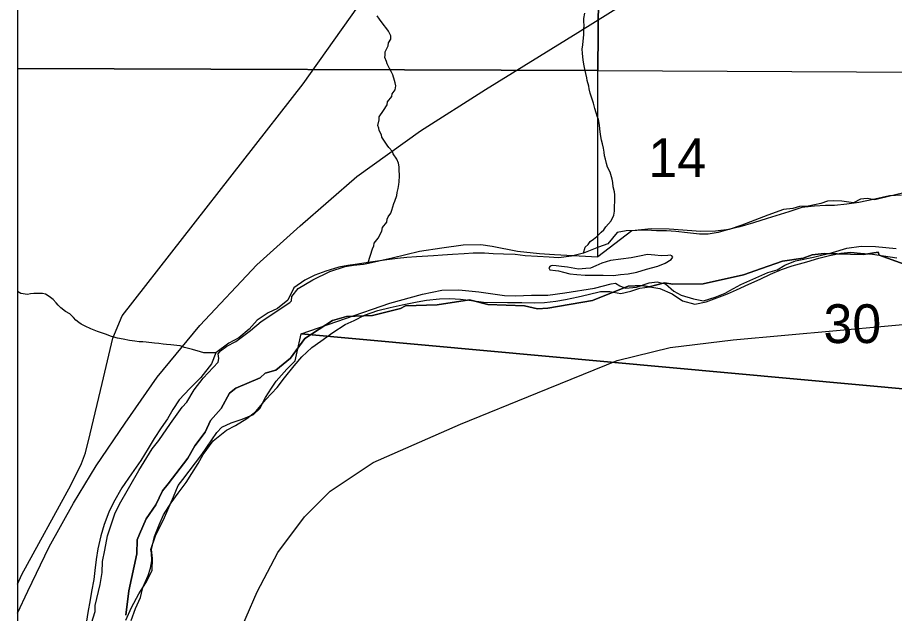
# Model space of a CAD drawing. Extents: x 0 to 34, y 0 to 22.
# Drawn here: x 16.6 to 17.545, y 18.951 to 19.593 of the extents above; entities that cross this region are included whole.
import ezdxf

# ---------------------------------------------------------------- set-up
doc = ezdxf.new("R2010")
doc.units = 0
for name, color, linetype in [('GM_X_County_Road', 7, 'Continuous'), ('GM_X_Major_River', 7, 'Continuous'), ('GM_X_Minor_River', 7, 'Continuous'), ('GM_X_Rail_Line', 7, 'Continuous'), ('GM_X_Section', 7, 'Continuous'), ('GM_X_Section_Text', 7, 'Continuous'), ('GM_X_Unincorporated', 7, 'Continuous'), ('SC_Scratch1', 7, 'Continuous'), ('SH_Border', 7, 'Continuous'), ('SH_Cut_Line', 7, 'Continuous')]:
    doc.layers.add(name, color=color, linetype=linetype)

msp = doc.modelspace()

# ---------------------------------------------------------------- linework, layer by layer
at = {"layer": 'GM_X_County_Road'}
for points in [[(16.59999, 18.98204), (16.60479, 18.99269), (16.65763, 19.08895), (16.66897, 19.11241), (16.67314, 19.12394), (16.67838, 19.14444), (16.69117, 19.19857), (16.70268, 19.24752), (16.71279, 19.27147), (16.90778, 19.52198), (16.96699, 19.60505), (16.99179, 19.63189), (17.03917, 19.66999), (17.08216, 19.70081), (17.10542, 19.71065), (17.1286, 19.71373), (17.2334, 19.71372), (17.27092, 19.71252), (17.32928, 19.71064), (17.33924, 19.71033), (17.44315, 19.70692), (17.53189, 19.70575), (17.64432, 19.69971)], [(16.83476, 18.91919), (16.85845, 18.97378), (16.88052, 19.01652), (16.90932, 19.05485), (16.9372, 19.0825), (16.98343, 19.11339), (17.07751, 19.15474), (17.16067, 19.18866), (17.24639, 19.2235), (17.30381, 19.23758), (17.3716, 19.24557), (17.59438, 19.26601)]]:
    msp.add_lwpolyline(points, dxfattribs=at)
at = {"layer": 'GM_X_Major_River'}
for points in [[(17.55306, 19.40187), (17.54015, 19.40098), (17.52415, 19.39749), (17.50701, 19.39402), (17.49407, 19.392), (17.48077, 19.39074), (17.47129, 19.39055), (17.45914, 19.39002), (17.44545, 19.38839), (17.4317, 19.38372), (17.40804, 19.37658), (17.39354, 19.37192), (17.37866, 19.36765), (17.36646, 19.36485), (17.3554, 19.36165), (17.34474, 19.35958), (17.33526, 19.35976), (17.32239, 19.36115), (17.3099, 19.36254), (17.29968, 19.36312), (17.28906, 19.36333), (17.27807, 19.36393), (17.26783, 19.36375), (17.25606, 19.36322), (17.24654, 19.3615), (17.23643, 19.34916), (17.2265, 19.34555), (17.21006, 19.33903), (17.1971, 19.33586), (17.18341, 19.33423), (17.17318, 19.33481), (17.16068, 19.33544), (17.14742, 19.33646), (17.13645, 19.33782), (17.12394, 19.33806), (17.11295, 19.33866), (17.10348, 19.33923), (17.09134, 19.33908), (17.08147, 19.33852), (17.06893, 19.33762), (17.05831, 19.33707), (17.04843, 19.3365), (17.0302, 19.33534), (17.01956, 19.33441), (17.00968, 19.33347), (16.99828, 19.33217), (16.97812, 19.32914), (16.9667, 19.32747), (16.95605, 19.32577), (16.94653, 19.32406), (16.93241, 19.31978), (16.92056, 19.31545), (16.90983, 19.30995), (16.89791, 19.30183), (16.89157, 19.28865), (16.88039, 19.27936), (16.87006, 19.275), (16.85851, 19.26687), (16.84959, 19.25716), (16.83841, 19.24787), (16.82767, 19.242), (16.8138, 19.23163), (16.80901, 19.21993), (16.79771, 19.20495), (16.78572, 19.1934), (16.77409, 19.18108), (16.76743, 19.17057), (16.76153, 19.16042), (16.75489, 19.15067), (16.74745, 19.13941), (16.74078, 19.12852), (16.73294, 19.11574), (16.72278, 19.10112), (16.71261, 19.08611), (16.70357, 19.07032), (16.69843, 19.05978), (16.69323, 19.04657), (16.68995, 19.03447), (16.68663, 19.02047), (16.68487, 19.00872), (16.6835, 18.99696), (16.68216, 18.98711), (16.67962, 18.97423), (16.67788, 18.96324)], [(16.71693, 18.94347), (16.72289, 18.95703), (16.73077, 18.97171), (16.73822, 18.98372), (16.74532, 18.99689), (16.74558, 19.00981), (16.74427, 19.01972), (16.74758, 19.03372), (16.75277, 19.04617), (16.75754, 19.0571), (16.76576, 19.06986), (16.77318, 19.08036), (16.78176, 19.09197), (16.78803, 19.10174), (16.79469, 19.11225), (16.8002, 19.12202), (16.81074, 19.13664), (16.82538, 19.14814), (16.83497, 19.15327), (16.84726, 19.16102), (16.8569, 19.16843), (16.86778, 19.18152), (16.8798, 19.19421), (16.88797, 19.2047), (16.8981, 19.2178), (16.90664, 19.22752), (16.91747, 19.23757), (16.92708, 19.24423), (16.93979, 19.25348), (16.95324, 19.26234), (16.96281, 19.26672), (16.97392, 19.2722), (16.98844, 19.27724), (17.00178, 19.28077), (17.01474, 19.28356), (17.03073, 19.28667), (17.04101, 19.28837), (17.05507, 19.28999), (17.06608, 19.29016), (17.07744, 19.28955), (17.08955, 19.28817), (17.10241, 19.2864), (17.12819, 19.28589), (17.14374, 19.28597), (17.15739, 19.2857), (17.16802, 19.28587), (17.18019, 19.28753), (17.19084, 19.28923), (17.20455, 19.292), (17.21522, 19.29445), (17.22857, 19.29799), (17.23842, 19.29779), (17.25052, 19.29566), (17.26119, 19.29811), (17.27111, 19.30133), (17.28177, 19.30303), (17.29235, 19.30092), (17.30588, 19.29533), (17.31711, 19.28788), (17.33031, 19.2842), (17.3425, 19.28663), (17.35396, 19.29096), (17.36543, 19.2953), (17.375, 19.29967), (17.3884, 19.30588), (17.40065, 19.31134), (17.41175, 19.31644), (17.42361, 19.32153), (17.43507, 19.32549), (17.45109, 19.32973), (17.46406, 19.33366), (17.47551, 19.33686), (17.48769, 19.33928), (17.49833, 19.34021), (17.50893, 19.33924), (17.52181, 19.33823), (17.53353, 19.33648), (17.5479, 19.3343)], [(17.1801, 19.32061), (17.18312, 19.32017), (17.18878, 19.31854), (17.19557, 19.31688), (17.20315, 19.31636), (17.21185, 19.31542), (17.2202, 19.31564), (17.23157, 19.31542), (17.24257, 19.3152), (17.25017, 19.31619), (17.25853, 19.31679), (17.26768, 19.31889), (17.27798, 19.32211), (17.29018, 19.32529), (17.29821, 19.32856), (17.30474, 19.33223), (17.30669, 19.33485), (17.30558, 19.33639), (17.3037, 19.33719), (17.30104, 19.33686), (17.29382, 19.33624), (17.28701, 19.33714), (17.27906, 19.33767), (17.27068, 19.33594), (17.26154, 19.33422), (17.25051, 19.33291), (17.23948, 19.33123), (17.22994, 19.32838), (17.22344, 19.32546), (17.21769, 19.32291), (17.21276, 19.32263), (17.20478, 19.32203), (17.19306, 19.32416), (17.18663, 19.32467), (17.18058, 19.32554), (17.17641, 19.32601)], [(17.17641, 19.32601), (17.17412, 19.32529), (17.17295, 19.32341), (17.17404, 19.32111), (17.1801, 19.32061)], [(16.67788, 18.96324), (16.67617, 18.95377), (16.674, 18.94013)]]:
    msp.add_lwpolyline(points, dxfattribs=at)
at = {"layer": 'GM_X_Minor_River'}
for points in [[(16.97812, 19.32914), (16.98273, 19.34401), (16.98427, 19.34703), (16.98467, 19.35006), (16.98887, 19.35533), (16.9927, 19.36288), (16.99349, 19.36704), (16.99807, 19.37269), (16.99847, 19.37572), (16.99962, 19.37836), (17.0023, 19.38251), (17.00345, 19.38554), (17.00462, 19.38932), (17.00578, 19.39272), (17.00693, 19.39537), (17.00887, 19.40142), (17.00927, 19.40482), (17.01043, 19.40899), (17.01122, 19.41315), (17.01162, 19.41618), (17.01167, 19.42263), (17.01134, 19.42946), (17.01136, 19.43249), (17.01063, 19.43629), (17.00877, 19.44048), (17.00503, 19.44621), (17.0043, 19.44887), (17.00017, 19.45308), (16.99867, 19.45575), (16.99269, 19.46415), (16.99233, 19.46681), (16.98971, 19.47138), (16.98935, 19.47404), (16.98862, 19.47708), (16.9898, 19.48314), (16.98982, 19.48617), (16.99441, 19.49296), (16.99861, 19.49937), (16.99902, 19.5024), (17.00359, 19.50805), (17.00399, 19.51108), (17.00705, 19.51522), (17.00784, 19.51977), (17.0071, 19.52281), (17.00637, 19.52547), (17.00452, 19.53156), (17.00266, 19.53499), (17.00117, 19.53841), (16.99856, 19.54337), (16.99782, 19.54603), (16.99596, 19.55022), (16.99636, 19.55287), (16.99638, 19.55628), (16.99945, 19.5627), (16.99986, 19.56612), (17.00253, 19.56988), (17.00256, 19.57368), (16.99995, 19.57863), (16.99808, 19.5813), (16.99433, 19.58627), (16.99021, 19.59162), (16.98759, 19.59506)], [(17.21006, 19.33903), (17.21191, 19.34567), (17.21533, 19.34867), (17.21725, 19.35169), (17.22105, 19.35431), (17.22447, 19.35731), (17.22942, 19.36181), (17.23209, 19.36444), (17.23438, 19.36746), (17.2401, 19.37423), (17.24279, 19.38027), (17.24358, 19.38444), (17.2436, 19.38785), (17.24405, 19.39695), (17.24409, 19.40226), (17.24373, 19.4053), (17.24226, 19.41062), (17.24192, 19.41556), (17.24118, 19.41898), (17.23897, 19.42658), (17.23599, 19.43192), (17.23488, 19.4361), (17.23378, 19.44066), (17.23267, 19.44409), (17.23232, 19.44826), (17.2316, 19.45244), (17.2305, 19.457), (17.22977, 19.46118), (17.22868, 19.46726), (17.22797, 19.47334), (17.22762, 19.47713), (17.22653, 19.48321), (17.22504, 19.48702), (17.22393, 19.49044), (17.22245, 19.49539), (17.22099, 19.50109), (17.21728, 19.51174), (17.21618, 19.51631), (17.21582, 19.51935), (17.21398, 19.52543), (17.21362, 19.52847), (17.2118, 19.53759), (17.21107, 19.54139), (17.20998, 19.54747), (17.20928, 19.55506), (17.20893, 19.55924), (17.20934, 19.56378), (17.21056, 19.57515), (17.2106, 19.58084), (17.21101, 19.58463), (17.21066, 19.58919), (17.21068, 19.59222), (17.21148, 19.5979)], [(16.8138, 19.23163), (16.80077, 19.23154), (16.79738, 19.23271), (16.7887, 19.23544), (16.78002, 19.23742), (16.77549, 19.23936), (16.77171, 19.23977), (16.76529, 19.24021), (16.76075, 19.24063), (16.75697, 19.24105), (16.75244, 19.24185), (16.74753, 19.24227), (16.73884, 19.24312), (16.73506, 19.24353), (16.73128, 19.24356), (16.72637, 19.24437), (16.7207, 19.24518), (16.7139, 19.24638), (16.70786, 19.24758), (16.70144, 19.24915), (16.69465, 19.25187), (16.68636, 19.2546), (16.67919, 19.2577), (16.67278, 19.26042), (16.66864, 19.26273), (16.66601, 19.26427), (16.663, 19.26696), (16.66037, 19.26964), (16.65624, 19.27385), (16.65172, 19.27617), (16.64684, 19.28038), (16.64383, 19.28307), (16.64158, 19.28574), (16.63858, 19.28918), (16.63557, 19.29149), (16.63294, 19.29303), (16.63031, 19.29495), (16.62691, 19.29574), (16.61745, 19.29583), (16.61405, 19.29548), (16.61064, 19.29476), (16.60346, 19.29558), (16.59999, 19.29803)]]:
    msp.add_lwpolyline(points, dxfattribs=at)
at = {"layer": 'GM_X_Rail_Line'}
msp.add_lwpolyline([(16.59999, 18.95076), (16.61116, 18.97452), (16.63408, 19.02238), (16.6602, 19.06971), (16.68468, 19.10968), (16.71607, 19.15596), (16.75065, 19.20539), (16.79638, 19.26119), (16.85811, 19.32663), (16.90485, 19.36883), (16.96582, 19.42177), (17.03437, 19.47131), (17.10449, 19.51565), (17.20408, 19.57711), (17.29361, 19.63325), (17.85099, 19.97327), (17.97357, 20.04812), (18.24489, 20.21712), (18.27648, 20.23613)], dxfattribs=at)
at = {"layer": 'GM_X_Section'}
for points in [[(17.55431, 19.40405), (17.52994, 19.39813), (17.52422, 19.39673), (17.51592, 19.39805), (17.50871, 19.39745), (17.50143, 19.39344), (17.48859, 19.39523), (17.47989, 19.39579), (17.47344, 19.39517), (17.46619, 19.39268), (17.45934, 19.39131), (17.45249, 19.38994), (17.44301, 19.38939), (17.43577, 19.38727), (17.4259, 19.38635), (17.40911, 19.38027), (17.38085, 19.36951), (17.36711, 19.36488), (17.35267, 19.36292), (17.33675, 19.3625), (17.30273, 19.36513), (17.28304, 19.36555), (17.26216, 19.36335), (17.22557, 19.33535), (17.22573, 19.34254), (17.22572, 19.5361), (18.20132, 19.53105)], [(17.76676, 19.17336), (16.90562, 19.25207), (17.0014, 19.28524), (17.03646, 19.29509), (17.05738, 19.29919), (17.07595, 19.29955), (17.09749, 19.29757), (17.12506, 19.29356), (17.1368, 19.29331), (17.15424, 19.29408), (17.17166, 19.29408), (17.18989, 19.29634), (17.22219, 19.30133), (17.2401, 19.30625), (17.24466, 19.30691), (17.24952, 19.30415), (17.25552, 19.30137), (17.26729, 19.30264), (17.28103, 19.30726), (17.28976, 19.30821), (17.29843, 19.30613), (17.30773, 19.29836), (17.31559, 19.29402), (17.32876, 19.28995), (17.3397, 19.28782), (17.35228, 19.29172), (17.36298, 19.29603), (17.36797, 19.29896), (17.37985, 19.30552), (17.40891, 19.31853), (17.41883, 19.32135), (17.42726, 19.32609), (17.43872, 19.33077), (17.45813, 19.3349), (17.47868, 19.33976), (17.49394, 19.34473), (17.50951, 19.34667), (17.52504, 19.34634), (17.54734, 19.34435)], [(16.72248, 18.94313), (16.72729, 18.95591), (16.73247, 18.96791), (16.73498, 18.97847), (16.74094, 18.9916), (16.74338, 18.9995), (16.74468, 19.00743), (16.7445, 19.01614), (16.74381, 19.01956), (16.74867, 19.03423), (16.75857, 19.05409), (16.76813, 19.07623), (16.77332, 19.08863), (16.77838, 19.09495), (16.79866, 19.12217), (16.8147, 19.14569), (16.82013, 19.15163), (16.83046, 19.15633), (16.84228, 19.16025), (16.85451, 19.16529), (16.86109, 19.17159), (16.8674, 19.18357), (16.87368, 19.19366), (16.87876, 19.20113), (16.8904, 19.21414), (16.89931, 19.22304), (16.90562, 19.25207), (17.76676, 19.17336)]]:
    msp.add_lwpolyline(points, dxfattribs=at)
at = {"layer": 'GM_X_Unincorporated'}
for points in [[(17.23188, 20.23613), (16.59999, 20.23613), (16.59999, 19.53848), (17.22572, 19.5361)], [(18.24929, 20.23613), (17.23188, 20.23613), (17.22572, 19.5361), (18.20132, 19.53105), (18.24282, 19.55857)]]:
    msp.add_lwpolyline(points, close=True, dxfattribs=at)
msp.add_lwpolyline([(16.67391, 18.92183), (16.68366, 18.95267), (16.6838, 18.95911), (16.68921, 18.98172), (16.69139, 18.99493), (16.69164, 19.00667), (16.69417, 19.01873), (16.69716, 19.0342), (16.70486, 19.0579), (16.71001, 19.06839), (16.73087, 19.10469), (16.745, 19.12825), (16.7524, 19.13718), (16.76491, 19.15547), (16.77741, 19.173), (16.78245, 19.17857), (16.79031, 19.19167), (16.80005, 19.20433), (16.81633, 19.22179), (16.81717, 19.22556), (16.81614, 19.23051), (16.81886, 19.23385), (16.82579, 19.239), (16.83537, 19.24411), (16.85115, 19.25589), (16.86272, 19.26548), (16.89346, 19.28604), (16.8954, 19.28789), (16.89588, 19.29243), (16.9025, 19.301), (16.91823, 19.3105), (16.93661, 19.31958), (16.95339, 19.3249), (16.96213, 19.32623), (16.97314, 19.32751), (16.97846, 19.32853), (17.00396, 19.33404), (17.03329, 19.34137), (17.05761, 19.34501), (17.0804, 19.34831), (17.09935, 19.34866), (17.11181, 19.34688), (17.13896, 19.34137), (17.16277, 19.33897), (17.17904, 19.33786), (17.22557, 19.33535), (17.22573, 19.34254), (17.22572, 19.5361), (16.59999, 19.53848), (16.59999, 18.52284)], dxfattribs=at)
at = {"layer": 'SC_Scratch1'}
for points in [[(19.25699, 20.23613), (16.59999, 20.23613), (16.59999, 18.07943)], [(16.71669, 18.94893), (16.72006, 18.97512), (16.72863, 19.01507), (16.72898, 19.03008), (16.73137, 19.03621), (16.73873, 19.05258), (16.74925, 19.06766), (16.75617, 19.08289), (16.76232, 19.09047), (16.78367, 19.11814), (16.79125, 19.13139), (16.80229, 19.14598), (16.80809, 19.15869), (16.81946, 19.17152), (16.82847, 19.18817), (16.83548, 19.19369), (16.86154, 19.20487), (16.86707, 19.20979), (16.87846, 19.21308), (16.89444, 19.22603), (16.90992, 19.24701), (16.93949, 19.26666), (16.95468, 19.27088), (16.98263, 19.27187), (17.01284, 19.27936), (17.0181, 19.2824), (17.05253, 19.28351), (17.08724, 19.28897), (17.10715, 19.28381), (17.14671, 19.28234), (17.16055, 19.27917), (17.17161, 19.27996), (17.21975, 19.28813), (17.25832, 19.30372), (17.27341, 19.30446), (17.28109, 19.30292), (17.29761, 19.30705), (17.30654, 19.30562), (17.33905, 19.30614), (17.38281, 19.31572), (17.4021, 19.32264), (17.4248, 19.33071), (17.44695, 19.33373), (17.45668, 19.33748), (17.46951, 19.33889), (17.51197, 19.33765), (17.528, 19.34012), (17.52901, 19.33689), (17.55591, 19.32727)], [(17.55591, 19.32727), (17.52901, 19.33689), (17.528, 19.34012), (17.51197, 19.33765), (17.46951, 19.33889), (17.45668, 19.33748), (17.44695, 19.33373), (17.4248, 19.33071), (17.4021, 19.32264), (17.38281, 19.31572), (17.33905, 19.30614), (17.30654, 19.30562), (17.29761, 19.30705), (17.28109, 19.30292), (17.27341, 19.30446), (17.25832, 19.30372), (17.21975, 19.28813), (17.17161, 19.27996), (17.16055, 19.27917), (17.14671, 19.28234), (17.10715, 19.28381), (17.08724, 19.28897), (17.05253, 19.28351), (17.0181, 19.2824), (17.01284, 19.27936), (16.98263, 19.27187), (16.95468, 19.27088), (16.93949, 19.26666), (16.90992, 19.24701), (16.89444, 19.22603), (16.87846, 19.21308), (16.86707, 19.20979), (16.86154, 19.20487), (16.83548, 19.19369), (16.82847, 19.18817), (16.81946, 19.17152), (16.80809, 19.15869), (16.80229, 19.14598), (16.79125, 19.13139), (16.78367, 19.11814), (16.76232, 19.09047), (16.75617, 19.08289), (16.74925, 19.06766), (16.73873, 19.05258), (16.73137, 19.03621), (16.72898, 19.03008), (16.72863, 19.01507), (16.72006, 18.97512), (16.71669, 18.94893)]]:
    msp.add_lwpolyline(points, dxfattribs=at)
at = {"layer": 'SH_Border'}
msp.add_lwpolyline([(16.59999, 20.23613), (16.59999, 13.43613), (23.39999, 13.43613), (23.39999, 20.23613), (16.59999, 20.23591)], dxfattribs=at)
at = {"layer": 'SH_Cut_Line'}
msp.add_lwpolyline([(19.25699, 20.23613), (16.59999, 20.23613), (16.59999, 13.43613)], dxfattribs=at)

# ---------------------------------------------------------------- texts
at = {"layer": 'GM_X_Section_Text'}
for s, p in [('14', (17.28019, 19.42129)), ('30', (17.46894, 19.24223))]:
    msp.add_text(s, height=0.041856, rotation=0.00001, dxfattribs=at).set_placement(p)

doc.saveas('drawing.dxf')
